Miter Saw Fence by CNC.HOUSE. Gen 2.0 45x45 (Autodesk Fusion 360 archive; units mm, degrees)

design "Gen 2.0 45x45" references "Type IA Cross Recessed Flat Countersunk Head Tapping Screw ANSI B18.6.5M M3x0.5 x 13 Type D Steel Grade 2 Plain", "Broached Hexagon Socket Head Cap Screw ANSI B18.3.1M - M5x0.8 x 25 Steel Grade 2 Plain", "Broached Hexagon Socket Head Cap Screw ANSI B18.3.1M - M8x1.25 x 35 Steel Grade 2 Plain", "Broached Hexagon Socket Head Cap Screw ANSI B18.3.1M - M8x1.25 x 25 Steel Grade 2 Plain", "Broached Hexagon Socket Head Cap Screw ANSI B18.3.1M - M6x1 x 16 Steel Grade 2 Plain", "Hexagon Thin Nut DIN 439-2 - M8 x 1.25 Steel 6 Plain", "Broached Hexagon Socket Head Cap Screw ANSI B18.3.1M - M5x0.8 x 12 Steel Grade 2 Plain", "Broached Hexagon Socket Head Cap Screw ANSI B18.3.1M - M6x1 x 20 Steel Grade 2 Plain", "Broached Hexagon Socket Flat Countersunk Head Cap Screw ASME B18.3.5M - M6x16 Steel Grade 2 Plain", "Broached Hexagon Socket Head Cap Screw ANSI B18.3.1M - M5x0.8 x 20 Steel Grade 2 Plain"
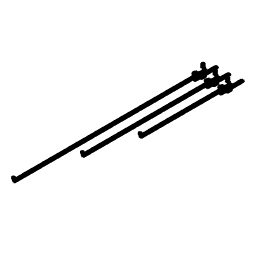
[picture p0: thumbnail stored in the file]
named bodies: "Bridge handle A=134", "50x100 (1) (1) (1) (1) (1) (1)", "Alu profile 45x45 (1) (1)", "Alu profile 45x45 (1) (1) (1)", "Alu profile 45x45 (1) (1) (1) (1)", "Cover cup 45x45"

design "Broached Hexagon Socket Head Cap Screw ANSI B18.3.1M - M5x0.8 x 20 Steel Grade 2 Plain"
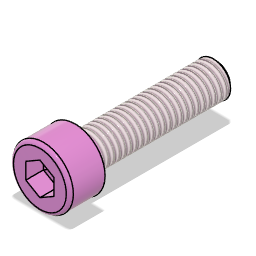
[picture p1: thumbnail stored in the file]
description: Broached Hexagon Socket Head Cap Screw ANSI B18.3.1M - M5x0.8 x 20
part number: arrangementsContainer
parameter "adsk_nomlen" = 20
parameter "adsk_headh" = 5
parameter "adsk_headdia" = 8.5
parameter "adsk_nomdia" = 5
parameter "adsk_philwidth" = 4
parameter "adsk_phildepth" = 2.5
parameter "adsk_thrlen" = 18.5185
parameter "adsk_startlen" = 0.4908
parameter "adsk_endpointdia" = 4.0185
sketch "Sketch1" plane through (0, 0, 0) normal (0, 1, 0) x axis (1, 0, 0)
  line L1 (-2.5, 20) -> (-2.5, 0)
  line L2 (0, 20) -> (-2.5, 20)
  line L3 (0, -5) -> (0, 20)
  line L4 (-4.25, 0) -> (-2.5, 0)
  line L5 (-4.25, -5) -> (-4.25, 0)
  line L6 (0, -5) -> (-4.25, -5)
  point P1 (0, 0)
  point P4 (0, 20)
  point P7 (0, -5)
  point P5 (-4.25, 0)
  point P6 (-4.25, -5)
  perpendicular L1 L2
  collinear P1 P4 P7
  perpendicular L1 L4
  coincident P1 L4
  vertical L1
  vertical L3
  parallel L3 L5
  coincident L3 P7
  perpendicular L3 L6
  dimension "d9" = 5 (= "adsk_nomdia")
  dimension "d66" = 8.5 (= "adsk_headdia")
  dimension "d68" distance P1 P4 = 20 (= "adsk_nomlen")
  dimension "d79" distance P5 P6 = 5 (= "adsk_headh")
revolve "Revolve1" sketch "Sketch1" AlongAngle 360
work_plane "WorkPlane1" AlongDistance 5 (= "adsk_headh")
sketch "Sketch6" plane through (0, 0, 5) normal (0, 0, 1) x axis (1, 0, 0)
  line L1 (2, 0) -> (-2, 0)
  line L2 (-2, 1.1547) -> (0, 0)
  line L3 (-2, 1.1547) -> (-2, -1.1547)
  line L4 (0, 0) -> (-2, -1.1547)
  point P1 (0, 0)
  point P4 (0, 0)
  point P2 (-2, 0)
  point P5 (-2, 1.1547)
  point P7 (-2, 1.1547)
  point P8 (0, 0)
  point P3 (2, 0)
  horizontal L1
  midpoint P1 L1
  coincident P1 P4
  perpendicular L1 L3
  midpoint P2 L3
  coincident P5 P7
  coincident P1 P8
  dimension "d72" distance P2 P3 = 4 (= "adsk_philwidth")
  dimension "d100" angle L1 L2 = 150
extrude "Extrude1" cut sketch "Sketch6" profile of L2 L3 L4 no distance stored
circular_pattern "C-Pattern1" TotalAngle 360
extrude "Extrude2" cut of existing geometry no distance stored taper -85
thread "Thread2" ThreadOffset 0 ThreadLength 18.5185 (= "adsk_thrlen")
fillet "Fillet4" radius 0.5 (= "adsk_nomdia * 0.1")
sketch "Sketch7" plane through (0, 0, 0) normal (0, 1, 0) x axis (1, 0, 0)
  line L1 (-2.55, 19.5092) -> (-2.55, 20)
  line L2 (-2.0092, 20) -> (-2.55, 19.5092)
  line L3 (0, -5) -> (0, 20)
  line L4 (0, 20) -> (-2.55, 20)
  point P5 (0, 20)
  point P7 (0, 20)
  point P4 (-2.0092, 20)
  point P3 (-2.55, 19.5092)
  point P1 (0, 0)
  coincident P5 P7
  perpendicular L3 L4
  coincident P4 L4
  perpendicular L1 L4
  dimension "d92" distance P3 P4 = 0.4908 (= "adsk_startlen")
  dimension "d98" distance P1 P4 = 2.0092 (= "adsk_endpointdia / 2")
  dimension "d99" distance P1 L1 = 2.55 (= "adsk_nomdia * 0.51")
revolve "Revolve3" sketch "Sketch7" AlongAngle 360
joint_origin "JointOrigin2" OffsetX 0 OffsetY 0 OffsetZ 0 AngleZ 0

design "Broached Hexagon Socket Head Cap Screw ANSI B18.3.1M - M5x0.8 x 25 Steel Grade 2 Plain"
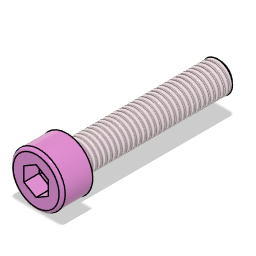
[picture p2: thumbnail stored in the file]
description: Broached Hexagon Socket Head Cap Screw ANSI B18.3.1M - M5x0.8 x 25
part number: arrangementsContainer
parameter "adsk_nomlen" = 25
parameter "adsk_headh" = 5
parameter "adsk_headdia" = 8.5
parameter "adsk_nomdia" = 5
parameter "adsk_philwidth" = 4
parameter "adsk_phildepth" = 2.5
parameter "adsk_thrlen" = 23.5185
parameter "adsk_startlen" = 0.4908
parameter "adsk_endpointdia" = 4.0185
sketch "Sketch1" plane through (0, 0, 0) normal (0, 1, 0) x axis (1, 0, 0)
  line L1 (-2.5, 25) -> (-2.5, 0)
  line L2 (0, 25) -> (-2.5, 25)
  line L3 (0, -5) -> (0, 25)
  line L4 (-4.25, 0) -> (-2.5, 0)
  line L5 (-4.25, -5) -> (-4.25, 0)
  line L6 (0, -5) -> (-4.25, -5)
  point P1 (0, 0)
  point P4 (0, 25)
  point P7 (0, -5)
  point P5 (-4.25, 0)
  point P6 (-4.25, -5)
  perpendicular L1 L2
  collinear P1 P4 P7
  perpendicular L1 L4
  coincident P1 L4
  vertical L1
  vertical L3
  parallel L3 L5
  coincident L3 P7
  perpendicular L3 L6
  dimension "d9" = 5 (= "adsk_nomdia")
  dimension "d66" = 8.5 (= "adsk_headdia")
  dimension "d68" distance P1 P4 = 25 (= "adsk_nomlen")
  dimension "d79" distance P5 P6 = 5 (= "adsk_headh")
revolve "Revolve1" sketch "Sketch1" AlongAngle 360
work_plane "WorkPlane1" AlongDistance 5 (= "adsk_headh")
sketch "Sketch6" plane through (0, 0, 5) normal (0, 0, 1) x axis (1, 0, 0)
  line L1 (2, 0) -> (-2, 0)
  line L2 (-2, 1.1547) -> (0, 0)
  line L3 (-2, 1.1547) -> (-2, -1.1547)
  line L4 (0, 0) -> (-2, -1.1547)
  point P1 (0, 0)
  point P4 (0, 0)
  point P2 (-2, 0)
  point P5 (-2, 1.1547)
  point P7 (-2, 1.1547)
  point P8 (0, 0)
  point P3 (2, 0)
  horizontal L1
  midpoint P1 L1
  coincident P1 P4
  perpendicular L1 L3
  midpoint P2 L3
  coincident P5 P7
  coincident P1 P8
  dimension "d72" distance P2 P3 = 4 (= "adsk_philwidth")
  dimension "d100" angle L1 L2 = 150
extrude "Extrude1" cut sketch "Sketch6" profile of L2 L3 L4 no distance stored
circular_pattern "C-Pattern1" TotalAngle 360
extrude "Extrude2" cut of existing geometry no distance stored taper -85
thread "Thread2" ThreadOffset 0 ThreadLength 23.5185 (= "adsk_thrlen")
fillet "Fillet4" radius 0.5 (= "adsk_nomdia * 0.1")
sketch "Sketch7" plane through (0, 0, 0) normal (0, 1, 0) x axis (1, 0, 0)
  line L1 (-2.55, 24.5092) -> (-2.55, 25)
  line L2 (-2.0092, 25) -> (-2.55, 24.5092)
  line L3 (0, -5) -> (0, 25)
  line L4 (0, 25) -> (-2.55, 25)
  point P5 (0, 25)
  point P7 (0, 25)
  point P4 (-2.0092, 25)
  point P3 (-2.55, 24.5092)
  point P1 (0, 0)
  coincident P5 P7
  perpendicular L3 L4
  coincident P4 L4
  perpendicular L1 L4
  dimension "d92" distance P3 P4 = 0.4908 (= "adsk_startlen")
  dimension "d98" distance P1 P4 = 2.0092 (= "adsk_endpointdia / 2")
  dimension "d99" distance P1 L1 = 2.55 (= "adsk_nomdia * 0.51")
revolve "Revolve3" sketch "Sketch7" AlongAngle 360
joint_origin "JointOrigin2" OffsetX 0 OffsetY 0 OffsetZ 0 AngleZ 0

design "Broached Hexagon Socket Head Cap Screw ANSI B18.3.1M - M6x1 x 20 Steel Grade 2 Plain"
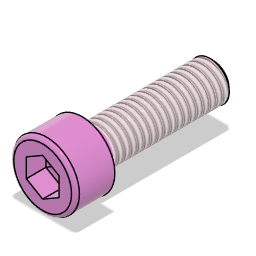
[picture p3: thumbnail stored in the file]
description: Broached Hexagon Socket Head Cap Screw ANSI B18.3.1M - M6x1 x 20
part number: arrangementsContainer
parameter "adsk_nomlen" = 20
parameter "adsk_headh" = 6
parameter "adsk_headdia" = 10
parameter "adsk_nomdia" = 6
parameter "adsk_philwidth" = 5
parameter "adsk_phildepth" = 3
parameter "adsk_thrlen" = 18.1731
parameter "adsk_startlen" = 0.6135
parameter "adsk_endpointdia" = 4.7731
sketch "Sketch1" plane through (0, 0, 0) normal (0, 1, 0) x axis (1, 0, 0)
  line L1 (-3, 20) -> (-3, 0)
  line L2 (0, 20) -> (-3, 20)
  line L3 (0, -6) -> (0, 20)
  line L4 (-5, 0) -> (-3, 0)
  line L5 (-5, -6) -> (-5, 0)
  line L6 (0, -6) -> (-5, -6)
  point P1 (0, 0)
  point P4 (0, 20)
  point P7 (0, -6)
  point P5 (-5, 0)
  point P6 (-5, -6)
  perpendicular L1 L2
  collinear P1 P4 P7
  perpendicular L1 L4
  coincident P1 L4
  vertical L1
  vertical L3
  parallel L3 L5
  coincident L3 P7
  perpendicular L3 L6
  dimension "d9" = 6 (= "adsk_nomdia")
  dimension "d66" = 10 (= "adsk_headdia")
  dimension "d68" distance P1 P4 = 20 (= "adsk_nomlen")
  dimension "d79" distance P5 P6 = 6 (= "adsk_headh")
revolve "Revolve1" sketch "Sketch1" AlongAngle 360
work_plane "WorkPlane1" AlongDistance 6 (= "adsk_headh")
sketch "Sketch6" plane through (0, 0, 6) normal (0, 0, 1) x axis (1, 0, 0)
  line L1 (2.5, 0) -> (-2.5, 0)
  line L2 (-2.5, 1.4434) -> (0, 0)
  line L3 (-2.5, 1.4434) -> (-2.5, -1.4434)
  line L4 (0, 0) -> (-2.5, -1.4434)
  point P1 (0, 0)
  point P4 (0, 0)
  point P2 (-2.5, 0)
  point P5 (-2.5, 1.4434)
  point P7 (-2.5, 1.4434)
  point P8 (0, 0)
  point P3 (2.5, 0)
  horizontal L1
  midpoint P1 L1
  coincident P1 P4
  perpendicular L1 L3
  midpoint P2 L3
  coincident P5 P7
  coincident P1 P8
  dimension "d72" distance P2 P3 = 5 (= "adsk_philwidth")
  dimension "d100" angle L1 L2 = 150
extrude "Extrude1" cut sketch "Sketch6" profile of L2 L3 L4 no distance stored
circular_pattern "C-Pattern1" TotalAngle 360
extrude "Extrude2" cut of existing geometry no distance stored taper -85
thread "Thread2" ThreadOffset 0 ThreadLength 18.1731 (= "adsk_thrlen")
fillet "Fillet4" radius 0.6 (= "adsk_nomdia * 0.1")
sketch "Sketch7" plane through (0, 0, 0) normal (0, 1, 0) x axis (1, 0, 0)
  line L1 (-3.06, 19.3866) -> (-3.06, 20)
  line L2 (-2.3866, 20) -> (-3.06, 19.3866)
  line L3 (0, -6) -> (0, 20)
  line L4 (0, 20) -> (-3.06, 20)
  point P5 (0, 20)
  point P7 (0, 20)
  point P4 (-2.3866, 20)
  point P3 (-3.06, 19.3866)
  point P1 (0, 0)
  coincident P5 P7
  perpendicular L3 L4
  coincident P4 L4
  perpendicular L1 L4
  dimension "d92" distance P3 P4 = 0.6135 (= "adsk_startlen")
  dimension "d98" distance P1 P4 = 2.3866 (= "adsk_endpointdia / 2")
  dimension "d99" distance P1 L1 = 3.06 (= "adsk_nomdia * 0.51")
revolve "Revolve3" sketch "Sketch7" AlongAngle 360
joint_origin "JointOrigin2" OffsetX 0 OffsetY 0 OffsetZ 0 AngleZ 0

design "Broached Hexagon Socket Head Cap Screw ANSI B18.3.1M - M6x1 x 16 Steel Grade 2 Plain"
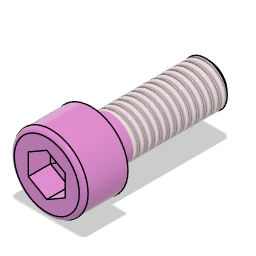
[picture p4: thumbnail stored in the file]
description: Broached Hexagon Socket Head Cap Screw ANSI B18.3.1M - M6x1 x 16
part number: arrangementsContainer
parameter "adsk_nomlen" = 16
parameter "adsk_headh" = 6
parameter "adsk_headdia" = 10
parameter "adsk_nomdia" = 6
parameter "adsk_philwidth" = 5
parameter "adsk_phildepth" = 3
parameter "adsk_thrlen" = 13.3866
parameter "adsk_startlen" = 0.6135
parameter "adsk_endpointdia" = 4.7731
sketch "Sketch1" plane through (0, 0, 0) normal (0, 1, 0) x axis (1, 0, 0)
  line L1 (-3, 16) -> (-3, 0)
  line L2 (0, 16) -> (-3, 16)
  line L3 (0, -6) -> (0, 16)
  line L4 (-5, 0) -> (-3, 0)
  line L5 (-5, -6) -> (-5, 0)
  line L6 (0, -6) -> (-5, -6)
  point P1 (0, 0)
  point P4 (0, 16)
  point P7 (0, -6)
  point P5 (-5, 0)
  point P6 (-5, -6)
  perpendicular L1 L2
  collinear P1 P4 P7
  perpendicular L1 L4
  coincident P1 L4
  vertical L1
  vertical L3
  parallel L3 L5
  coincident L3 P7
  perpendicular L3 L6
  dimension "d9" = 6 (= "adsk_nomdia")
  dimension "d66" = 10 (= "adsk_headdia")
  dimension "d68" distance P1 P4 = 16 (= "adsk_nomlen")
  dimension "d79" distance P5 P6 = 6 (= "adsk_headh")
revolve "Revolve1" sketch "Sketch1" AlongAngle 360
work_plane "WorkPlane1" AlongDistance 6 (= "adsk_headh")
sketch "Sketch6" plane through (0, 0, 6) normal (0, 0, 1) x axis (1, 0, 0)
  line L1 (2.5, 0) -> (-2.5, 0)
  line L2 (-2.5, 1.4434) -> (0, 0)
  line L3 (-2.5, 1.4434) -> (-2.5, -1.4434)
  line L4 (0, 0) -> (-2.5, -1.4434)
  point P1 (0, 0)
  point P4 (0, 0)
  point P2 (-2.5, 0)
  point P5 (-2.5, 1.4434)
  point P7 (-2.5, 1.4434)
  point P8 (0, 0)
  point P3 (2.5, 0)
  horizontal L1
  midpoint P1 L1
  coincident P1 P4
  perpendicular L1 L3
  midpoint P2 L3
  coincident P5 P7
  coincident P1 P8
  dimension "d72" distance P2 P3 = 5 (= "adsk_philwidth")
  dimension "d100" angle L1 L2 = 150
extrude "Extrude1" cut sketch "Sketch6" profile of L2 L3 L4 no distance stored
circular_pattern "C-Pattern1" TotalAngle 360
extrude "Extrude2" cut of existing geometry no distance stored taper -85
thread "Thread2" ThreadOffset 0 ThreadLength 13.3866 (= "adsk_thrlen")
fillet "Fillet4" radius 0.6 (= "adsk_nomdia * 0.1")
sketch "Sketch7" plane through (0, 0, 0) normal (0, 1, 0) x axis (1, 0, 0)
  line L1 (-3.06, 15.3866) -> (-3.06, 16)
  line L2 (-2.3866, 16) -> (-3.06, 15.3866)
  line L3 (0, -6) -> (0, 16)
  line L4 (0, 16) -> (-3.06, 16)
  point P5 (0, 16)
  point P7 (0, 16)
  point P4 (-2.3866, 16)
  point P3 (-3.06, 15.3866)
  point P1 (0, 0)
  coincident P5 P7
  perpendicular L3 L4
  coincident P4 L4
  perpendicular L1 L4
  dimension "d92" distance P3 P4 = 0.6135 (= "adsk_startlen")
  dimension "d98" distance P1 P4 = 2.3866 (= "adsk_endpointdia / 2")
  dimension "d99" distance P1 L1 = 3.06 (= "adsk_nomdia * 0.51")
revolve "Revolve3" sketch "Sketch7" AlongAngle 360
joint_origin "JointOrigin2" OffsetX 0 OffsetY 0 OffsetZ 0 AngleZ 0

design "Type IA Cross Recessed Flat Countersunk Head Tapping Screw ANSI B18.6.5M M3x0.5 x 13 Type D Steel Grade 2 Plain"
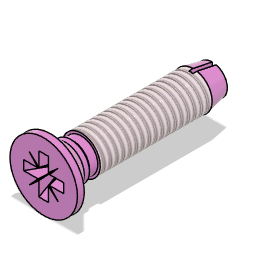
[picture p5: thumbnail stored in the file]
description: Part Number
part number: arrangementsContainer
parameter "adsk_nomlen" = 13
parameter "adsk_headh" = 1.7
parameter "adsk_headdia" = 5.2
parameter "adsk_nomdia" = 3
parameter "adsk_headang" = 90
parameter "adsk_phildia" = 3.08
parameter "adsk_philwidth" = 0.73
parameter "adsk_phildepth" = 2.08
parameter "adsk_startlen" = 1.8
parameter "adsk_endpointdia" = 2.32
parameter "adsk_thrlen" = 10.1
parameter "adsk_grpdia" = 2.86
parameter "adsk_grplen" = 0.4
parameter "adsk_shlang" = 45
sketch "Sketch1" plane through (0, 0, 0) normal (0, 1, 0) x axis (1, 0, 0)
  line L1 (-2.6, -3.13) -> (0, -3.13)
  line L2 (-2.6, -2.6) -> (-2.6, -3.13)
  line L3 (-1.43, -1.43) -> (-2.6, -2.6)
  line L4 (0, 0) -> (-1.43, -1.43)
  line L5 (0, 9.87) -> (-1.5, 9.87)
  line L6 (0, -3.13) -> (0, 9.87)
  line L7 (-1.43, -1.03) -> (-1.43, -1.43)
  line L8 (-1.275, -0.875) -> (-1.43, -1.03)
  line L9 (-1.275, -0.23) -> (-1.275, -0.875)
  line L10 (-1.5, -0.23) -> (-1.275, -0.23)
  line L11 (-1.5, 9.87) -> (-1.5, -0.23)
  point P1 (0, 0)
  point P2 (0, -3.13)
  point P8 (0, 9.87)
  point P5 (0, 0)
  point P6 (-1.43, -1.43)
  point P9 (-1.43, -1.03)
  horizontal L1
  perpendicular L1 L2
  collinear L3 L4
  perpendicular L1 L6
  collinear P1 P2 P8
  coincident P5 L6
  coincident P1 L4
  vertical L7
  parallel L7 L9
  horizontal L10
  vertical L11
  dimension "d5" angle L4 L6 = 45 (= "adsk_headang * 0.5")
  dimension "d9" = 3 (= "adsk_nomdia")
  dimension "d10" distance P2 P8 = 13 (= "adsk_nomlen")
  dimension "d11" = 5.2 (= "adsk_headdia")
  dimension "d80" distance L1 P6 = 1.7 (= "adsk_headh")
  dimension "d107" = 2.86 (= "adsk_grpdia")
  dimension "d108" distance P6 P9 = 0.4 (= "adsk_grplen")
  dimension "d109" angle L7 L8 = 45 (= "adsk_shlang")
  dimension "d110" = 2.55 (= "adsk_nomdia * 0.85")
  dimension "d111" distance L5 L10 = 10.1 (= "adsk_thrlen")
revolve "Revolve1" sketch "Sketch1" AlongAngle 360
sketch "Sketch7" plane through (0, 0, 3.13) normal (0, 0, 1) x axis (1, 0, 0)
  line L1 (0.438, 0.438) -> (-0.438, 0.438)
  line L2 (0.438, -0.438) -> (0.438, 0.438)
  line L3 (-0.438, -0.438) -> (0.438, -0.438)
  line L4 (-0.438, 0.438) -> (-0.438, -0.438)
  line L5 (0.438, -0.438) -> (-0.438, 0.438)
  line L6 (-0.438, -0.438) -> (0.438, 0.438)
  circle C1 centre (0, 0) radius 2.6
  point P7 (0, 0)
  point P1 (0, 0)
  point P3 (-0.438, 0.438)
  point P4 (0.438, 0.438)
  horizontal L1
  perpendicular L1 L2
  parallel L1 L3
  parallel L2 L4
  coincident L5 P7
  coincident L6 P7
  coincident P1 P7
  equal L1 L4
  dimension "d65" distance P3 P4 = 0.876 (= "adsk_philwidth * 1.2")
extrude "Extrude4" new body sketch "Sketch7" profile of L1 L2 L3 L4 against normal blind 1.664 (magnitude of "-adsk_phildepth * 0.8") taper -10
sketch "Sketch2" plane through (0, 0, 3.13) normal (0, 0, 1) x axis (1, 0, 0)
  line L1 (-0.365, 0.365) -> (-0.365, 1.54)
  line L2 (-1.54, 0.365) -> (-0.365, 0.365)
  line L3 (0, 1.54) -> (0, 0)
  line L4 (1.54, 0.365) -> (0.365, 0.365)
  line L5 (0.365, 0.365) -> (0.365, 1.54)
  line L6 (1.54, -0.365) -> (0.365, -0.365)
  line L7 (0.365, -0.365) -> (0.365, -1.54)
  line L8 (-0.365, -0.365) -> (-0.365, -1.54)
  line L9 (-1.54, -0.365) -> (-0.365, -0.365)
  line L10 (0.365, 1.54) -> (-0.365, 1.54)
  line L11 (-1.54, -0.365) -> (-1.54, 0.365)
  line L12 (0.365, -1.54) -> (-0.365, -1.54)
  line L13 (1.54, 0.365) -> (1.54, -0.365)
  line L14 (0, 22.5) -> (0, 1.75)
  line L15 (22.5, 0) -> (1.75, 0)
  circle C1 centre (0, 0) radius 2.6
  point P2 (0, 0)
  point P7 (0, 0)
  point P3 (-0.365, 1.54)
  point P10 (0.365, 1.54)
  point P4 (-0.365, 0.365)
  point P9 (0.365, 0.365)
  point P5 (-1.54, 0.365)
  point P8 (1.54, 0.365)
  point P6 (0, 1.54)
  perpendicular L1 L2
  coincident P2 P7
  symmetric P3 L3 P10
  symmetric P4 L3 P9
  symmetric P5 L3 P8
  perpendicular L5 L10
  perpendicular L9 L11
  equal L10 L11
  equal L1 L2
  symmetric L2 L9 L15
  vertical L3
  symmetric L4 L6 L15
  collinear L5 L7
  symmetric L10 L12 L15
  coincident P6 L10
  dimension "d22" distance P3 P10 = 0.73 (= "adsk_philwidth")
  dimension "d57" distance L11 L13 = 3.08 (= "adsk_phildia")
extrude "Extrude1" new body sketch "Sketch2" profile of L1 L2 L4 L5 L6 L7 L8 L9 L10 L11 L12 L13 no distance stored taper -6
draft "Draft1" Angle1 30 Angle2 0
combine "Combine1"
sketch "Sketch6" plane through (0, 0, 3.13) normal (0, 0, 1) x axis (1, 0, 0)
  line L1 (-1.1191, 1.1191) -> (0, 0)
  line L2 (-0.365, 0.438) -> (-1.1191, 1.1191)
  line L3 (-0.438, 0.365) -> (-0.365, 0.438)
  line L4 (-1.1191, 1.1191) -> (-0.438, 0.365)
  circle C1 centre (0, 0) radius 1.5827
  point P1 (0, 0)
  point P2 (0, 0)
  point P3 (-0.365, 1.54)
  point P4 (0, 0)
  point P5 (-1.1191, 1.1191)
  point P6 (-0.438, 0.438)
  point P7 (-0.365, 0.438)
  point P9 (-0.365, 0.438)
  point P8 (-0.438, 0.365)
  point P10 (-0.438, 0.365)
  coincident P1 P2
  coincident C1 P3
  coincident P1 P4
  coincident C1 P5
  coincident L1 P6
  perpendicular L1 L3
  coincident P7 P9
  coincident P8 P10
extrude "Extrude2" cut sketch "Sketch6" profile of L2 L3 L4 no distance stored taper -30
circular_pattern "C-Pattern1" TotalAngle 360
thread "Thread1" ThreadOffset 0 ThreadLength 10
sketch "Sketch5" plane through (0, 0, 0) normal (0, 1, 0) x axis (1, 0, 0)
  line L1 (-1.53, 8.07) -> (-1.53, 9.87)
  line L2 (-1.16, 9.87) -> (-1.53, 8.07)
  line L3 (0, -3.13) -> (0, 9.87)
  line L4 (0, 9.87) -> (-1.53, 9.87)
  point P5 (0, 9.87)
  point P7 (0, 9.87)
  point P4 (-1.16, 9.87)
  point P1 (0, 0)
  point P3 (-1.53, 8.07)
  vertical L1
  coincident P5 P7
  perpendicular L3 L4
  coincident P4 L4
  dimension "d93" distance P1 L1 = 1.53 (= "adsk_nomdia * 0.51")
  dimension "d94" distance P1 P4 = 1.16 (= "adsk_endpointdia / 2")
  dimension "d95" distance P3 P4 = 1.8 (= "adsk_startlen")
revolve "Revolve2" sketch "Sketch5" AlongAngle 360
sketch "Sketch8" plane through (0, 0, -9.87) normal (0, 0, -1) x axis (-1, 0, 0)
  line L1 (0, 0) -> (0, 2.6)
  line L2 (-0.3, 0) -> (0, 0)
  line L3 (-0.3, 2.6) -> (-0.3, 0)
  line L4 (0, 2.6) -> (-0.3, 2.6)
  point P1 (0, 0)
  point P4 (0, 0)
  point P3 (0, 2.6)
  coincident P1 P4
  horizontal L2
  perpendicular L1 L4
  dimension "d81" distance L1 L3 = 0.3 (= "adsk_nomdia / 10")
  dimension "d101" distance P3 P4 = 2.6 (= "adsk_headdia / 2")
extrude "Extrude5" cut sketch "Sketch8" no distance stored
joint_origin "JointOrigin2" OffsetX 0 OffsetY 0 OffsetZ 0 AngleZ 0
joint_origin "JointOrigin3" OffsetX 0 OffsetY 0 OffsetZ 3.2 (= "( adsk_nomdia * 0.5 ) * tan(90 deg - adsk_headang * 0.5) + adsk_headh") AngleZ 0

design "Broached Hexagon Socket Head Cap Screw ANSI B18.3.1M - M5x0.8 x 12 Steel Grade 2 Plain"
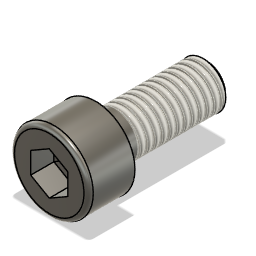
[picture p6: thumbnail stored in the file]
description: Broached Hexagon Socket Head Cap Screw ANSI B18.3.1M - M5x0.8 x 12
part number: arrangementsContainer
parameter "adsk_nomlen" = 12
parameter "adsk_headh" = 5
parameter "adsk_headdia" = 8.5
parameter "adsk_nomdia" = 5
parameter "adsk_philwidth" = 4
parameter "adsk_phildepth" = 2.5
parameter "adsk_thrlen" = 9.9092
parameter "adsk_startlen" = 0.4908
parameter "adsk_endpointdia" = 4.0185
sketch "Sketch1" plane through (0, 0, 0) normal (0, 1, 0) x axis (1, 0, 0)
  line L1 (-2.5, 12) -> (-2.5, 0)
  line L2 (0, 12) -> (-2.5, 12)
  line L3 (0, -5) -> (0, 12)
  line L4 (-4.25, 0) -> (-2.5, 0)
  line L5 (-4.25, -5) -> (-4.25, 0)
  line L6 (0, -5) -> (-4.25, -5)
  point P1 (0, 0)
  point P4 (0, 12)
  point P7 (0, -5)
  point P5 (-4.25, 0)
  point P6 (-4.25, -5)
  perpendicular L1 L2
  collinear P1 P4 P7
  perpendicular L1 L4
  coincident P1 L4
  vertical L1
  vertical L3
  parallel L3 L5
  coincident L3 P7
  perpendicular L3 L6
  dimension "d9" = 5 (= "adsk_nomdia")
  dimension "d66" = 8.5 (= "adsk_headdia")
  dimension "d68" distance P1 P4 = 12 (= "adsk_nomlen")
  dimension "d79" distance P5 P6 = 5 (= "adsk_headh")
revolve "Revolve1" sketch "Sketch1" AlongAngle 360
work_plane "WorkPlane1" AlongDistance 5 (= "adsk_headh")
sketch "Sketch6" plane through (0, 0, 5) normal (0, 0, 1) x axis (1, 0, 0)
  line L1 (2, 0) -> (-2, 0)
  line L2 (-2, 1.1547) -> (0, 0)
  line L3 (-2, 1.1547) -> (-2, -1.1547)
  line L4 (0, 0) -> (-2, -1.1547)
  point P1 (0, 0)
  point P4 (0, 0)
  point P2 (-2, 0)
  point P5 (-2, 1.1547)
  point P7 (-2, 1.1547)
  point P8 (0, 0)
  point P3 (2, 0)
  horizontal L1
  midpoint P1 L1
  coincident P1 P4
  perpendicular L1 L3
  midpoint P2 L3
  coincident P5 P7
  coincident P1 P8
  dimension "d72" distance P2 P3 = 4 (= "adsk_philwidth")
  dimension "d100" angle L1 L2 = 150
extrude "Extrude1" cut sketch "Sketch6" profile of L2 L3 L4 no distance stored
circular_pattern "C-Pattern1" TotalAngle 360
extrude "Extrude2" cut of existing geometry no distance stored taper -85
thread "Thread2" ThreadOffset 0 ThreadLength 9.9092 (= "adsk_thrlen")
fillet "Fillet4" radius 0.5 (= "adsk_nomdia * 0.1")
sketch "Sketch7" plane through (0, 0, 0) normal (0, 1, 0) x axis (1, 0, 0)
  line L1 (-2.55, 11.5092) -> (-2.55, 12)
  line L2 (-2.0092, 12) -> (-2.55, 11.5092)
  line L3 (0, -5) -> (0, 12)
  line L4 (0, 12) -> (-2.55, 12)
  point P5 (0, 12)
  point P7 (0, 12)
  point P4 (-2.0092, 12)
  point P3 (-2.55, 11.5092)
  point P1 (0, 0)
  coincident P5 P7
  perpendicular L3 L4
  coincident P4 L4
  perpendicular L1 L4
  dimension "d92" distance P3 P4 = 0.4908 (= "adsk_startlen")
  dimension "d98" distance P1 P4 = 2.0092 (= "adsk_endpointdia / 2")
  dimension "d99" distance P1 L1 = 2.55 (= "adsk_nomdia * 0.51")
revolve "Revolve3" sketch "Sketch7" AlongAngle 360
joint_origin "JointOrigin2" OffsetX 0 OffsetY 0 OffsetZ 0 AngleZ 0

design "Hexagon Thin Nut DIN 439-2 - M8 x 1.25 Steel 6 Plain"
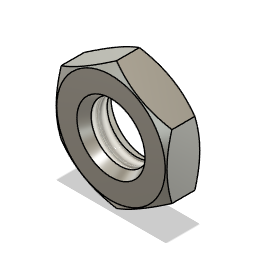
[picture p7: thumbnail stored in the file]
description: Hexagon Thin Nut DIN 439-2 - M8 x 1.25
part number: arrangementsContainer
parameter "adsk_nheig" = 4
parameter "adsk_maxdia" = 15.015
parameter "adsk_nomdia" = 8
parameter "adsk_waflat" = 13
parameter "adsk_chamang1" = 30
parameter "adsk_chamang2" = 30
parameter "adsk_beardia" = 12.74 (= "adsk_waflat * 0.98")
sketch "Sketch1" plane through (0, 0, 0) normal (0, 1, 0) x axis (1, 0, 0)
  line L1 (0, -4) -> (0, 0)
  line L2 (-6.37, 0) -> (-4, 0)
  line L3 (-7.5075, -0.6567) -> (-6.37, 0)
  line L4 (-7.5075, -3.3433) -> (-7.5075, -0.6567)
  line L5 (-6.37, -4) -> (-7.5075, -3.3433)
  line L6 (-4, -4) -> (-6.37, -4)
  line L7 (-4, 0) -> (-4, -4)
  point P3 (0, -4)
  point P1 (0, 0)
  point P2 (0, 0)
  point P10 (0, 0)
  point P4 (-4, 0)
  point P9 (-4, -4)
  vertical L1
  coincident L1 P3
  coincident P1 L1
  horizontal L2
  perpendicular L2 L4
  perpendicular L4 L6
  perpendicular L6 L7
  coincident P1 L2
  coincident P2 P10
  coincident P3 L6
  equal L2 L6
  dimension "d121" = 8 (= "adsk_nomdia")
  dimension "d122" angle L2 L3 = 30 (= "adsk_chamang1")
  dimension "d123" angle L5 L6 = 30 (= "adsk_chamang2")
  dimension "d126" distance P4 P9 = 4 (= "adsk_nheig")
  dimension "d128" = 15.015 (= "adsk_maxdia")
  dimension "d172" = 12.74 (= "adsk_beardia")
revolve "Revolve1" sketch "Sketch1" AlongAngle 360
sketch "Sketch8" plane through (0, 0, 4) normal (0, 0, 1) x axis (1, 0, 0)
  line L1 (-13, 0) -> (0, 0)
  line L2 (-6.5, 3.7567) -> (-6.5, -3.7567)
  circle C1 centre (0, 0) radius 4
  circle C2 centre (0, 0) radius 7.5075
  point P1 (0, 0)
  point P2 (0, 0)
  point P5 (-6.5, 3.7567)
  horizontal L1
  perpendicular L1 L2
  midpoint L1 L2
  coincident P1 P2
  coincident P5 C2
  dimension "d114" distance P1 L2 = 6.5 (= "adsk_waflat / 2")
extrude "Extrude5" cut sketch "Sketch8" profile of L2 C2 no distance stored
circular_pattern "C-Pattern2" TotalAngle 360
thread "Thread3" ThreadOffset 0 ThreadLength 10
sketch "Sketch12" plane through (0, 0, 0) normal (0, 1, 0) x axis (1, 0, 0)
  line L1 (-3.3898, -4) -> (3.3898, -4)
  line L2 (-6.37, -4) -> (6.37, -4)
  line L3 (-6.37, 0) -> (6.37, 0)
  line L4 (-3.3898, 0) -> (3.3898, 0)
  line L5 (0, 0) -> (-4, 0)
  line L6 (-4, 0) -> (-2.8453, -2)
  line L7 (0, -4) -> (-4, -4)
  line L8 (-4, -4) -> (-2.8453, -2)
  line L9 (0, -4) -> (0, 0)
  point P12 (-2.8453, -2)
  point P15 (-2.8453, -2)
  point P10 (-4, 0)
  point P13 (-4, -4)
  point P14 (0, -4)
  point P17 (0, -4)
  point P1 (0, 0)
  point P11 (0, 0)
  horizontal L5
  collinear L2 L7
  coincident P12 P15
  vertical P10 P13
  coincident L2 P14
  coincident P14 P17
  coincident P1 P11
  dimension "d165" angle L3 L6 = 60
  dimension "d169" angle L7 L8 = 60
  dimension "d170" distance P10 P11 = 4 (= "adsk_nomdia * 0.5")
revolve "Revolve3" sketch "Sketch12" AlongAngle 360
joint_origin "JointOrigin9" OffsetX 0 OffsetY 0 OffsetZ 0 AngleZ 0
joint_origin "JointOrigin10" OffsetX 0 OffsetY 0 OffsetZ 4 (= "adsk_nheig") AngleZ 0

design "Broached Hexagon Socket Head Cap Screw ANSI B18.3.1M - M8x1.25 x 35 Steel Grade 2 Plain"
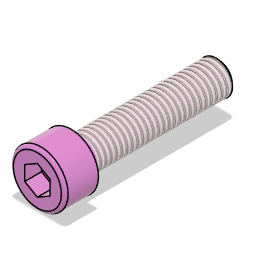
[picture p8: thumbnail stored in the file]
description: Broached Hexagon Socket Head Cap Screw ANSI B18.3.1M - M8x1.25 x 35
part number: arrangementsContainer
parameter "adsk_nomlen" = 35
parameter "adsk_headh" = 8
parameter "adsk_headdia" = 13
parameter "adsk_nomdia" = 8
parameter "adsk_philwidth" = 6
parameter "adsk_phildepth" = 4
parameter "adsk_thrlen" = 32.6664
parameter "adsk_startlen" = 0.7668
parameter "adsk_endpointdia" = 6.4664
sketch "Sketch1" plane through (0, 0, 0) normal (0, 1, 0) x axis (1, 0, 0)
  line L1 (-4, 35) -> (-4, 0)
  line L2 (0, 35) -> (-4, 35)
  line L3 (0, -8) -> (0, 35)
  line L4 (-6.5, 0) -> (-4, 0)
  line L5 (-6.5, -8) -> (-6.5, 0)
  line L6 (0, -8) -> (-6.5, -8)
  point P1 (0, 0)
  point P4 (0, 35)
  point P7 (0, -8)
  point P5 (-6.5, 0)
  point P6 (-6.5, -8)
  perpendicular L1 L2
  collinear P1 P4 P7
  perpendicular L1 L4
  coincident P1 L4
  vertical L1
  vertical L3
  parallel L3 L5
  coincident L3 P7
  perpendicular L3 L6
  dimension "d9" = 8 (= "adsk_nomdia")
  dimension "d66" = 13 (= "adsk_headdia")
  dimension "d68" distance P1 P4 = 35 (= "adsk_nomlen")
  dimension "d79" distance P5 P6 = 8 (= "adsk_headh")
revolve "Revolve1" sketch "Sketch1" AlongAngle 360
work_plane "WorkPlane1" AlongDistance 8 (= "adsk_headh")
sketch "Sketch6" plane through (0, 0, 8) normal (0, 0, 1) x axis (1, 0, 0)
  line L1 (3, 0) -> (-3, 0)
  line L2 (-3, 1.7321) -> (0, 0)
  line L3 (-3, 1.7321) -> (-3, -1.7321)
  line L4 (0, 0) -> (-3, -1.7321)
  point P1 (0, 0)
  point P4 (0, 0)
  point P2 (-3, 0)
  point P5 (-3, 1.7321)
  point P7 (-3, 1.7321)
  point P8 (0, 0)
  point P3 (3, 0)
  horizontal L1
  midpoint P1 L1
  coincident P1 P4
  perpendicular L1 L3
  midpoint P2 L3
  coincident P5 P7
  coincident P1 P8
  dimension "d72" distance P2 P3 = 6 (= "adsk_philwidth")
  dimension "d100" angle L1 L2 = 150
extrude "Extrude1" cut sketch "Sketch6" profile of L2 L3 L4 no distance stored
circular_pattern "C-Pattern1" TotalAngle 360
extrude "Extrude2" cut of existing geometry no distance stored taper -85
thread "Thread2" ThreadOffset 0 ThreadLength 32.6664 (= "adsk_thrlen")
fillet "Fillet4" radius 0.8 (= "adsk_nomdia * 0.1")
sketch "Sketch7" plane through (0, 0, 0) normal (0, 1, 0) x axis (1, 0, 0)
  line L1 (-4.08, 34.2332) -> (-4.08, 35)
  line L2 (-3.2332, 35) -> (-4.08, 34.2332)
  line L3 (0, -8) -> (0, 35)
  line L4 (0, 35) -> (-4.08, 35)
  point P5 (0, 35)
  point P7 (0, 35)
  point P4 (-3.2332, 35)
  point P3 (-4.08, 34.2332)
  point P1 (0, 0)
  coincident P5 P7
  perpendicular L3 L4
  coincident P4 L4
  perpendicular L1 L4
  dimension "d92" distance P3 P4 = 0.7668 (= "adsk_startlen")
  dimension "d98" distance P1 P4 = 3.2332 (= "adsk_endpointdia / 2")
  dimension "d99" distance P1 L1 = 4.08 (= "adsk_nomdia * 0.51")
revolve "Revolve3" sketch "Sketch7" AlongAngle 360
joint_origin "JointOrigin2" OffsetX 0 OffsetY 0 OffsetZ 0 AngleZ 0

design "Broached Hexagon Socket Flat Countersunk Head Cap Screw ASME B18.3.5M - M6x16 Steel Grade 2 Plain"
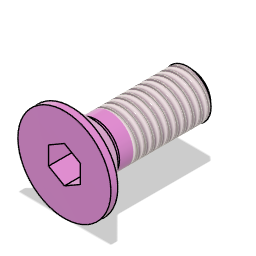
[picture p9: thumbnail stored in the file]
description: Broached Hexagon Socket Flat Countersunk Head Cap Screw ASME B18.3.5M - M6x16
part number: arrangementsContainer
parameter "adsk_nomlen" = 16
parameter "adsk_headh" = 3.72
parameter "adsk_headdia" = 11.7
parameter "adsk_nomdia" = 6
parameter "adsk_headang" = 90
parameter "adsk_philwidth" = 4
parameter "adsk_phildepth" = 2.2
parameter "adsk_thrlen" = 10.28
parameter "adsk_midfillet" = 0.5
parameter "adsk_startlen" = 0.6 (= "adsk_nomdia * 0.1")
parameter "adsk_endpointdia" = 4.8 (= "adsk_nomdia - 2 * adsk_startlen")
sketch "Sketch1" plane through (0, 0, 0) normal (0, 1, 0) x axis (1, 0, 0)
  line L1 (-5.85, -6.72) -> (0, -6.72)
  line L2 (-5.85, -5.85) -> (-5.85, -6.72)
  line L3 (-3, -3) -> (-5.85, -5.85)
  line L4 (-3, 9.28) -> (-3, -3)
  line L5 (0, 0) -> (-3, -3)
  line L6 (0, 9.28) -> (-3, 9.28)
  line L7 (0, -6.72) -> (0, 9.28)
  point P1 (0, 0)
  point P2 (0, -6.72)
  point P8 (0, 9.28)
  point P5 (0, 0)
  point P3 (-5.85, -6.72)
  point P6 (-3, -3)
  perpendicular L1 L2
  vertical L4
  perpendicular L4 L6
  collinear L3 L5
  perpendicular L1 L7
  collinear P1 P2 P8
  coincident P5 L7
  coincident P1 L5
  horizontal L1
  dimension "d5" angle L5 L7 = 45 (= "adsk_headang * 0.5")
  dimension "d9" = 6 (= "adsk_nomdia")
  dimension "d10" distance P2 P8 = 16 (= "adsk_nomlen")
  dimension "d72" distance P3 P6 = 3.72 (= "adsk_headh")
  dimension "d73" = 11.7 (= "adsk_headdia")
revolve "Revolve1" sketch "Sketch1" AlongAngle 360
sketch "Sketch6" plane through (0, 0, 6.72) normal (0, 0, 1) x axis (1, 0, 0)
  line L1 (2, 0) -> (-2, 0)
  line L2 (-2, 1.1547) -> (-2, -1.1547)
  line L3 (0, 0) -> (-2, 1.1547)
  line L4 (0, 0) -> (-2, -1.1547)
  circle C1 centre (0, 0) radius 5.85
  point P1 (0, 0)
  point P7 (0, 0)
  point P3 (-2, 0)
  point P4 (2, 0)
  horizontal L1
  midpoint P1 L1
  perpendicular L1 L2
  coincident P1 P7
  midpoint P3 L2
  dimension "d65" distance P3 P4 = 4 (= "adsk_philwidth")
  dimension "d67" angle L3 L4 = 60
extrude "Extrude1" cut sketch "Sketch6" profile of L2 L3 L4 no distance stored
circular_pattern "C-Pattern1" TotalAngle 360
extrude "Extrude2" cut of existing geometry no distance stored
fillet "Fillet6" radius 0.5 (= "adsk_midfillet")
thread "Thread2" ThreadOffset 0 ThreadLength 10.28 (= "adsk_thrlen")
sketch "Sketch8" plane through (0, 0, 0) normal (0, 1, 0) x axis (1, 0, 0)
  line L1 (-5.85, -5.85) -> (-5.85, -6.72)
  line L2 (-3, -3) -> (-5.85, -5.85)
  line L3 (0, -6.72) -> (0, 9.28)
  line L4 (-5.85, -6.72) -> (0, -6.72)
  line L5 (-3.06, 9.28) -> (0, 9.28)
  line L6 (-3.06, 8.68) -> (-3.06, 9.28)
  line L7 (-2.4, 9.28) -> (-3.06, 8.68)
  point P6 (0, 9.28)
  point P10 (0, 9.28)
  point P13 (-2.4, 9.28)
  point P1 (0, 0)
  point P11 (-3.06, 9.28)
  point P12 (-3.06, 8.68)
  coincident P6 P10
  perpendicular L3 L5
  perpendicular L5 L6
  coincident L5 P13
  dimension "d104" distance P1 P13 = 2.4 (= "adsk_endpointdia / 2")
  dimension "d106" distance P1 P11 = 3.06 (= "adsk_nomdia * 0.51")
  dimension "d107" distance P11 P12 = 0.6 (= "adsk_startlen")
revolve "Revolve3" sketch "Sketch8" AlongAngle 360
joint_origin "JointOrigin1" OffsetX 0 OffsetY 0 OffsetZ 0 AngleZ 0
joint_origin "JointOrigin3" OffsetX 0 OffsetY 0 OffsetZ 6.72 (= "( adsk_nomdia / 2 ) * tan(90 deg - adsk_headang / 2) + adsk_headh") AngleZ 0

design "Broached Hexagon Socket Head Cap Screw ANSI B18.3.1M - M8x1.25 x 25 Steel Grade 2 Plain"
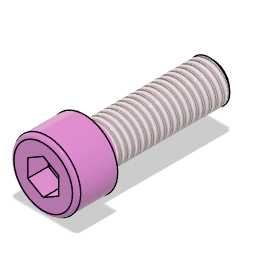
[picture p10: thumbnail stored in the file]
description: Broached Hexagon Socket Head Cap Screw ANSI B18.3.1M - M8x1.25 x 25
part number: arrangementsContainer
parameter "adsk_nomlen" = 25
parameter "adsk_headh" = 8
parameter "adsk_headdia" = 13
parameter "adsk_nomdia" = 8
parameter "adsk_philwidth" = 6
parameter "adsk_phildepth" = 4
parameter "adsk_thrlen" = 22.6664
parameter "adsk_startlen" = 0.7668
parameter "adsk_endpointdia" = 6.4664
sketch "Sketch1" plane through (0, 0, 0) normal (0, 1, 0) x axis (1, 0, 0)
  line L1 (-4, 25) -> (-4, 0)
  line L2 (0, 25) -> (-4, 25)
  line L3 (0, -8) -> (0, 25)
  line L4 (-6.5, 0) -> (-4, 0)
  line L5 (-6.5, -8) -> (-6.5, 0)
  line L6 (0, -8) -> (-6.5, -8)
  point P1 (0, 0)
  point P4 (0, 25)
  point P7 (0, -8)
  point P5 (-6.5, 0)
  point P6 (-6.5, -8)
  perpendicular L1 L2
  collinear P1 P4 P7
  perpendicular L1 L4
  coincident P1 L4
  vertical L1
  vertical L3
  parallel L3 L5
  coincident L3 P7
  perpendicular L3 L6
  dimension "d9" = 8 (= "adsk_nomdia")
  dimension "d66" = 13 (= "adsk_headdia")
  dimension "d68" distance P1 P4 = 25 (= "adsk_nomlen")
  dimension "d79" distance P5 P6 = 8 (= "adsk_headh")
revolve "Revolve1" sketch "Sketch1" AlongAngle 360
work_plane "WorkPlane1" AlongDistance 8 (= "adsk_headh")
sketch "Sketch6" plane through (0, 0, 8) normal (0, 0, 1) x axis (1, 0, 0)
  line L1 (3, 0) -> (-3, 0)
  line L2 (-3, 1.7321) -> (0, 0)
  line L3 (-3, 1.7321) -> (-3, -1.7321)
  line L4 (0, 0) -> (-3, -1.7321)
  point P1 (0, 0)
  point P4 (0, 0)
  point P2 (-3, 0)
  point P5 (-3, 1.7321)
  point P7 (-3, 1.7321)
  point P8 (0, 0)
  point P3 (3, 0)
  horizontal L1
  midpoint P1 L1
  coincident P1 P4
  perpendicular L1 L3
  midpoint P2 L3
  coincident P5 P7
  coincident P1 P8
  dimension "d72" distance P2 P3 = 6 (= "adsk_philwidth")
  dimension "d100" angle L1 L2 = 150
extrude "Extrude1" cut sketch "Sketch6" profile of L2 L3 L4 no distance stored
circular_pattern "C-Pattern1" TotalAngle 360
extrude "Extrude2" cut of existing geometry no distance stored taper -85
thread "Thread2" ThreadOffset 0 ThreadLength 22.6664 (= "adsk_thrlen")
fillet "Fillet4" radius 0.8 (= "adsk_nomdia * 0.1")
sketch "Sketch7" plane through (0, 0, 0) normal (0, 1, 0) x axis (1, 0, 0)
  line L1 (-4.08, 24.2332) -> (-4.08, 25)
  line L2 (-3.2332, 25) -> (-4.08, 24.2332)
  line L3 (0, -8) -> (0, 25)
  line L4 (0, 25) -> (-4.08, 25)
  point P5 (0, 25)
  point P7 (0, 25)
  point P4 (-3.2332, 25)
  point P3 (-4.08, 24.2332)
  point P1 (0, 0)
  coincident P5 P7
  perpendicular L3 L4
  coincident P4 L4
  perpendicular L1 L4
  dimension "d92" distance P3 P4 = 0.7668 (= "adsk_startlen")
  dimension "d98" distance P1 P4 = 3.2332 (= "adsk_endpointdia / 2")
  dimension "d99" distance P1 L1 = 4.08 (= "adsk_nomdia * 0.51")
revolve "Revolve3" sketch "Sketch7" AlongAngle 360
joint_origin "JointOrigin2" OffsetX 0 OffsetY 0 OffsetZ 0 AngleZ 0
